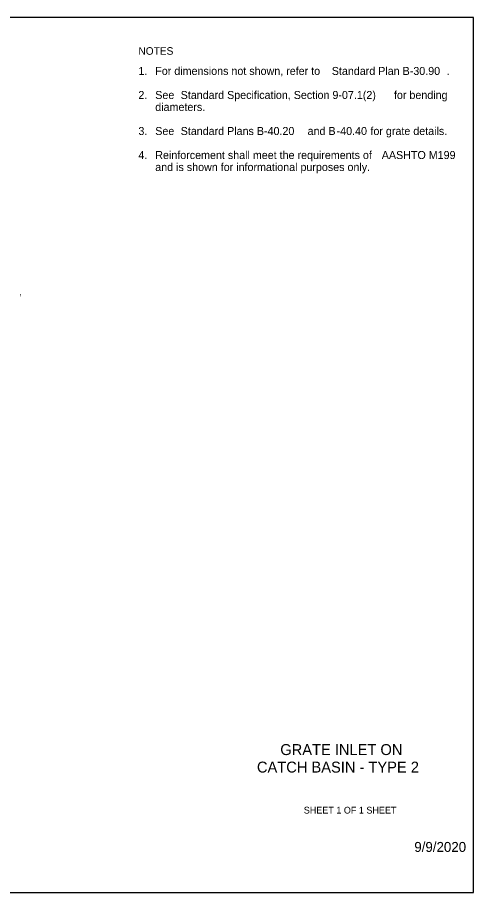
# Model space of a CAD drawing. Extents: x 99862 to 103151, y 100000 to 102076.
# Drawn here: x 102069 to 103151, y 100000 to 102076 of the extents above; entities that cross this region are included whole.
import ezdxf

# ---------------------------------------------------------------- set-up
doc = ezdxf.new("R2010")
doc.units = 0
for name, color, linetype in [('Level 1', 7, 'Continuous'), ('Level 15', 7, 'Continuous'), ('Level 20', 7, 'Continuous'), ('Level 60', 7, 'Continuous'), ('Level 62', 7, 'Continuous')]:
    doc.layers.add(name, color=color, linetype=linetype)

msp = doc.modelspace()

# ---------------------------------------------------------------- linework, layer by layer
at = {"layer": 'Level 1'}
msp.add_lwpolyline([(99862, 99999.5), (103151, 99999.5), (103151, 102075.5), (99862, 102075.5)], close=True, dxfattribs=at)
at = {"layer": 'Level 60'}
msp.add_line((103151, 102075.5), (103151, 102075.5), dxfattribs=at)

# ---------------------------------------------------------------- texts
at = {"layer": 'Level 15'}
msp.add_text('9/9/2020', height=23.62, dxfattribs=at).set_placement((103010.5, 100095.8))
at = {"layer": 'Level 20'}
for s, height, p in [('NOTES', 18, (102355.8, 101987.1)), ('1.', 19, (102355.8, 101939.2)), ('For dimensions not shown, refer to ', 19, (102395.8, 101939.2)), ('Standard Plan B-30.90', 19, (102814.7, 101939.2)), ('.', 19, (103087.2, 101939.2)), ('2.', 19, (102355.8, 101882.2)), ('See ', 19, (102395.8, 101882.2)), ('Standard Specification, Section 9-07.1(2)', 19, (102456.1, 101882.2)), (' for bending ', 19, (102955.2, 101882.2)), ('diameters.', 19, (102395.8, 101853.7)), ('3.', 19, (102355.8, 101796.7)), ('See ', 19, (102395.8, 101796.7)), ('Standard Plans B-40.20 ', 19, (102456.1, 101796.7)), ('and B', 19, (102757.3, 101796.7)), ('-40.40', 19, (102826.2, 101796.7)), (' for grate details.', 19, (102899.4, 101796.7)), ('4.', 19, (102355.8, 101739.7)), ('Reinforcement shall meet the requirements of ', 19, (102395.8, 101739.7)), ('AASHTO M199', 19, (102933.3, 101739.7)), ('and is shown for informational purposes only. ', 19, (102395.8, 101711.2)), (',', 16, (102073.4, 101416.7))]:
    msp.add_text(s, height=height, dxfattribs=at).set_placement(p)
at = {"layer": 'Level 62'}
for s, height, p in [('GRATE INLET ON ', 26, (102692.5, 100325.6)), ('CATCH BASIN - TYPE 2', 26, (102637.1, 100284)), ('SHEET 1 OF 1 SHEET', 16, (102748.2, 100186.8))]:
    msp.add_text(s, height=height, dxfattribs=at).set_placement(p)

doc.saveas('drawing.dxf')
